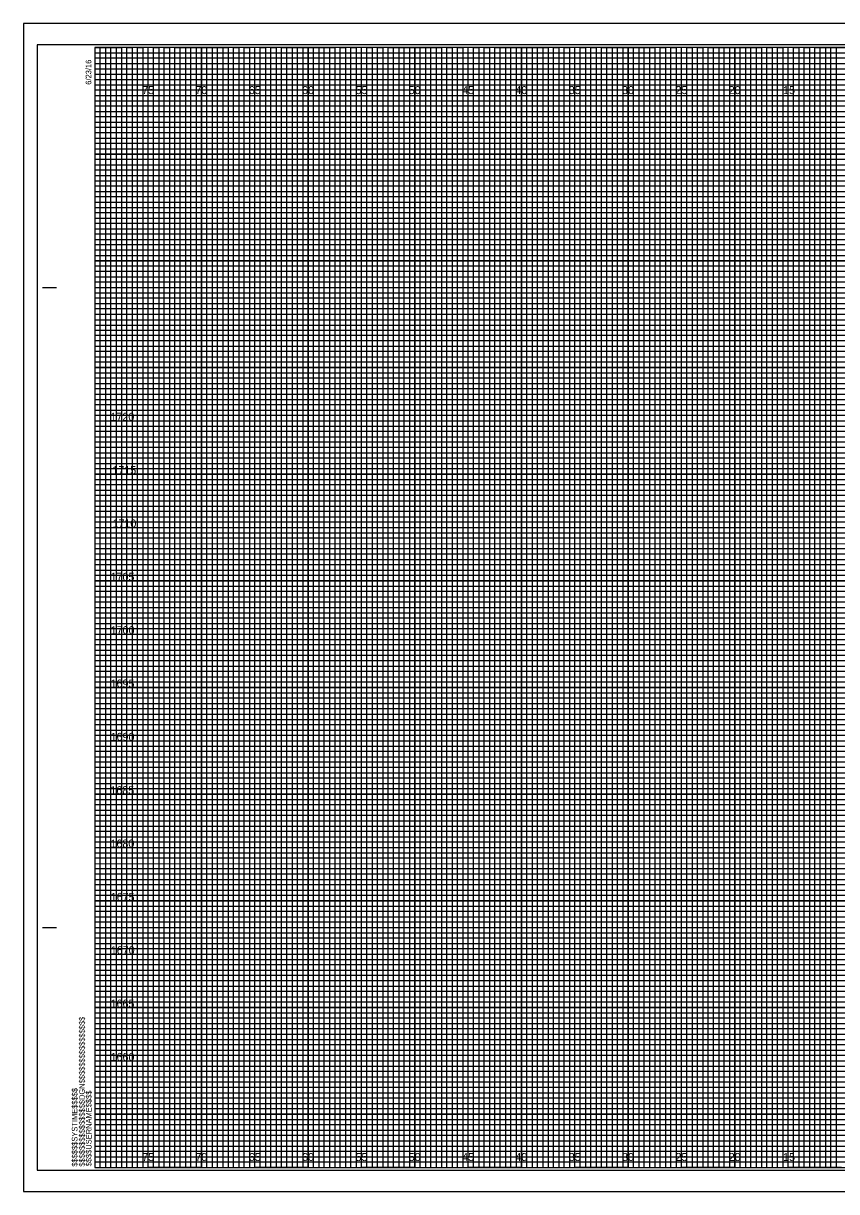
# Model space of a CAD drawing. Extents: x -7 to 162, y -2 to 327.
# Drawn here: x -6.7 to 69.5, y -2.3 to 107.3 of the extents above; entities that cross this region are included whole.
import ezdxf

# ---------------------------------------------------------------- set-up
doc = ezdxf.new("R2010")
doc.units = 0
for name, color, linetype in [('Raster_Level_0', 7, 'Continuous'), ('Scratch_Level_3', 7, 'Continuous'), ('Sheet Cross Section CELL', 7, 'Continuous'), ('Sheet Cross Section Grid Major CELL', 7, 'Continuous'), ('Sheet Cross Section Grid Middle CELL', 7, 'Continuous'), ('Sheet Cross Section Grid Minor 1 CELL', 7, 'Continuous'), ('Sheet Cross Section Grid Minor 2 CELL', 7, 'Continuous'), ('Sheet Cutting Line CELL', 7, 'Continuous'), ('Sheet DOT Grid CELL', 7, 'Continuous'), ('Sheet Plot Border Inside CELL', 7, 'Continuous'), ('Sheet Plot Border Outside CELL', 7, 'Continuous')]:
    doc.layers.add(name, color=color, linetype=linetype)

msp = doc.modelspace()

# ---------------------------------------------------------------- linework, layer by layer
at = {"layer": 'Sheet Cross Section CELL'}
for p, q in [((-4.9, 82.5), (-3.65, 82.5)), ((-4.85, 82.5), (-3.6, 82.5)), ((-4.9, 22.5), (-3.65, 22.5)), ((-4.85, 22.5), (-3.6, 22.5)), ((0, 0), (0, 0)), ((0, 0), (0, 0)), ((0, 0), (0, 0)), ((0, 0), (0, 0)), ((0, 0), (0, 0)), ((0, 0), (0, 0)), ((0, 0), (0, 0))]:
    msp.add_line(p, q, dxfattribs=at)
msp.add_lwpolyline([(160, 105), (0, 105), (0, 0), (160, 0)], close=True, dxfattribs=at)
at = {"layer": 'Sheet Cross Section Grid Major CELL'}
for p, q in [((5, 105), (0, 105)), ((5, 0), (5, 105)), ((15, 105), (10, 105)), ((10, 105), (10, 0)), ((15, 0), (15, 105)), ((25, 105), (20, 105)), ((20, 105), (20, 0)), ((25, 0), (25, 105)), ((35, 105), (30, 105)), ((30, 105), (30, 0)), ((35, 0), (35, 105)), ((45, 105), (40, 105)), ((40, 105), (40, 0)), ((45, 0), (45, 105)), ((55, 105), (50, 105)), ((50, 105), (50, 0)), ((55, 0), (55, 105)), ((65, 105), (60, 105)), ((60, 105), (60, 0)), ((65, 0), (65, 105)), ((10, 0), (5, 0)), ((20, 0), (15, 0)), ((30, 0), (25, 0)), ((40, 0), (35, 0)), ((50, 0), (45, 0)), ((60, 0), (55, 0)), ((70, 0), (65, 0))]:
    msp.add_line(p, q, dxfattribs=at)
for points in [[(0, 100), (160, 100), (160, 95), (0, 95)], [(0, 90), (160, 90), (160, 85), (0, 85)], [(0, 80), (160, 80), (160, 75), (0, 75)], [(0, 70), (160, 70), (160, 65), (0, 65)], [(0, 60), (160, 60), (160, 55), (0, 55)], [(0, 50), (160, 50), (160, 45), (0, 45)], [(0, 40), (160, 40), (160, 35), (0, 35)], [(0, 30), (160, 30), (160, 25), (0, 25)], [(0, 20), (160, 20), (160, 15), (0, 15)], [(0, 10), (160, 10), (160, 5), (0, 5)]]:
    msp.add_lwpolyline(points, dxfattribs=at)
at = {"layer": 'Sheet Cross Section Grid Middle CELL'}
for points in [[(0, 105), (2.5, 105), (2.5, 0), (7.5, 0), (7.5, 105), (12.5, 105), (12.5, 0), (17.5, 0), (17.5, 105), (22.5, 105), (22.5, 0), (27.5, 0), (27.5, 105), (32.5, 105), (32.5, 0), (37.5, 0), (37.5, 105), (42.5, 105), (42.5, 0), (47.5, 0), (47.5, 105), (52.5, 105), (52.5, 0), (57.5, 0), (57.5, 105), (62.5, 105), (62.5, 0), (67.5, 0), (67.5, 105), (72.5, 105)], [(0, 102.5), (137.5, 102.5)], [(0, 92.5), (160, 92.5), (160, 97.5), (0, 97.5)], [(0, 82.5), (160, 82.5), (160, 87.5), (0, 87.5)], [(0, 72.5), (160, 72.5), (160, 77.5), (0, 77.5)], [(0, 62.5), (160, 62.5), (160, 67.5), (0, 67.5)], [(0, 52.5), (160, 52.5), (160, 57.5), (0, 57.5)], [(0, 42.5), (160, 42.5), (160, 47.5), (0, 47.5)], [(0, 32.5), (160, 32.5), (160, 37.5), (0, 37.5)], [(0, 22.5), (160, 22.5), (160, 27.5), (0, 27.5)], [(0, 12.5), (160, 12.5), (160, 17.5), (0, 17.5)], [(0, 2.5), (160, 2.5), (160, 7.5), (0, 7.5)]]:
    msp.add_lwpolyline(points, dxfattribs=at)
at = {"layer": 'Sheet Cross Section Grid Minor 1 CELL'}
for p, q in [((0, 104.5), (130, 104.5)), ((130, 103.99), (0, 103.99)), ((0, 103.99), (0, 103.5)), ((0, 103.5), (130, 103.5)), ((130, 102.95), (0, 102.95)), ((0, 102.95), (0, 102)), ((0, 102), (160, 102))]:
    msp.add_line(p, q, dxfattribs=at)
for points in [[(0, 101.5), (135, 101.5), (160, 101.5), (160, 101), (0, 101)], [(0, 100.5), (160, 100.5), (160, 99.5), (0, 99.5)], [(0, 99), (160, 99), (160, 98.5), (0, 98.49)], [(0, 98), (160, 98), (160, 97), (0, 97)], [(0, 96.5), (160, 96.5), (160, 96), (0, 96)], [(0, 95.5), (160, 95.5), (160, 94.5), (0, 94.5)], [(0, 94), (160, 94), (160, 93.5), (0, 93.5)], [(0, 93), (160, 93), (160, 92), (0, 92)], [(0, 91.5), (160, 91.5), (160, 91), (0, 91)], [(0, 90.5), (160, 90.5), (160, 89.5), (0, 89.5)], [(0, 89), (160, 89), (160, 88.5), (0, 88.5)], [(0, 88), (160, 88), (160, 86.98), (160, 86.5), (160, 86), (0, 86)], [(0, 87), (160, 87), (160, 86.5), (0, 86.5)], [(0, 85.5), (160, 85.5), (160, 84.5), (0, 84.52)], [(0, 84.52), (160, 84.5), (160, 84), (0, 84)], [(0, 83.5), (160, 83.5), (160, 83), (0, 83)], [(0, 82), (160, 82), (160, 81.5), (0, 81.5)], [(0, 81), (160, 81), (160, 80.5), (0, 80.5)], [(-0.04, 79.45), (160, 79.45), (160, 78.94), (-0.04, 78.94)], [(0, 78.5), (160, 78.5), (160, 78), (0, 78)], [(0, 77), (160, 77), (160, 76.5), (0, 76.5)], [(0, 76), (160, 76), (160, 75.5), (0, 75.5)], [(0, 74.5), (160, 74.5), (160, 74), (0, 74)], [(0, 73.5), (160, 73.5), (160, 73), (0, 73)], [(0, 72), (160, 72), (160, 71.5), (0, 71.5)], [(0, 71), (160, 71), (160, 70.5), (0, 70.5)], [(0, 69.5), (160, 69.5), (160, 68.99), (0, 69)], [(0, 68.5), (160, 68.5), (160, 68), (0, 68)], [(0, 67), (160, 67), (160, 66.5), (0, 66.5)], [(0, 66), (160, 66), (160, 65.5), (0, 65.5)], [(0, 64.5), (160, 64.5), (160, 64), (0, 64)], [(0, 63.5), (160, 63.5), (160, 63), (0, 63)], [(0, 62), (160, 62), (160, 61.5), (0, 61.5)], [(0, 61), (160, 61), (160, 60.5), (0, 60.5)], [(0, 59.5), (160, 59.5), (160, 59), (0, 59)], [(0, 58.5), (160.03, 58.45), (160, 58), (0, 58)], [(0, 57), (160, 57), (160, 56.5), (0, 56.5)], [(0, 56), (160, 56), (160, 55.5), (0, 55.5)], [(0, 54.5), (160, 54.5), (160, 54), (0, 54)], [(0, 53.5), (160, 53.5), (160, 53), (0, 53)], [(0, 52), (160, 52), (160, 51.5), (0, 51.5)], [(0, 51), (160, 51), (160, 50.5), (0, 50.5)], [(0, 49.5), (160, 49.5), (160, 49), (0, 49)], [(0, 48.5), (160, 48.5), (160, 48), (0, 48)], [(0, 47), (160, 47), (160, 46.5), (0, 46.5)], [(0, 46), (160, 46), (160, 45.5), (0, 45.5)], [(0, 44.5), (160, 44.5), (160, 44), (0, 44)], [(0, 43.5), (160, 43.5), (160, 43), (0, 43)], [(0, 42), (160, 42), (160, 41.5), (0, 41.5)], [(0, 41), (160, 41), (160, 40.5), (0, 40.5)], [(0, 39.5), (160, 39.5), (160, 38.99), (0, 39)], [(0, 38.5), (160, 38.5), (160, 38), (0, 38)], [(0, 37), (160, 37), (160, 36.5), (0, 36.5)], [(0, 36), (160, 36), (160, 35.5), (0, 35.5)], [(0, 34.5), (160, 34.5), (160, 34), (0, 34)], [(0, 33.5), (160, 33.5), (160, 33), (0, 33)], [(0, 32), (160, 32), (160, 31.5), (0, 31.5)], [(0, 31), (160, 31), (160, 30.5), (0, 30.5)], [(0, 29.5), (160, 29.5), (160, 29), (0, 29)], [(0, 28.5), (160.03, 28.46), (160, 28), (0, 28)], [(0, 27), (160, 27), (160, 26.5), (0, 26.5)], [(0, 26), (160, 26), (160, 25.5), (0, 25.5)], [(0, 24.5), (160, 24.5), (160, 24), (0, 24)], [(0, 23.5), (160, 23.5), (160, 23), (0, 23)], [(0, 22), (160, 22), (160, 21.5), (0, 21.5)], [(0, 21), (160, 21), (160, 20.5), (0, 20.5)], [(0, 19.5), (160, 19.5), (160, 19), (0, 19)], [(0, 18.5), (160, 18.5), (160, 18), (0, 18)], [(0, 17), (160, 17), (160, 16.5), (0, 16.5)], [(0, 16), (160, 16), (160, 15.5), (0, 15.5)], [(0, 14.5), (160, 14.5), (160, 14), (0, 14)], [(0, 13.5), (160, 13.5), (160, 13), (0, 13)], [(0, 12), (160, 12), (160, 11.5), (0, 11.5)], [(0, 11), (160, 11), (160, 10.5), (0, 10.5)], [(0, 9.5), (160, 9.5), (160, 9), (0, 9)], [(0, 8.5), (160, 8.5), (160, 8), (0, 8)], [(0, 7), (160, 7), (160, 6.5), (0, 6.5)], [(0, 6), (160, 6), (160, 5.5), (0, 5.5)], [(0, 4.5), (160, 4.5), (160, 4), (0, 4)], [(0, 3.5), (160, 3.5), (160, 3), (0, 3)], [(0, 2), (160, 2), (160, 1.5), (0, 1.5)], [(0, 1), (160, 1), (160, 0.5), (0, 0.5)]]:
    msp.add_lwpolyline(points, dxfattribs=at)
at = {"layer": 'Sheet Cross Section Grid Minor 2 CELL'}
for points in [[(0, 0), (0.5, 0), (0.5, 105), (1, 105), (1, 0)], [(1, 0), (1.5, 0), (1.5, 105), (2, 105), (2, 0)], [(2.5, 0), (3, 0), (3, 105), (3.5, 105), (3.5, 0)], [(3.5, 0), (4, 0), (4, 105), (4.5, 105), (4.5, 0)], [(5, 0), (5.5, 0), (5.5, 105), (6, 105), (6, 0)], [(6, 0), (6.5, 0), (6.5, 105), (7, 105), (7, 0)], [(7.5, 0), (8, 0), (8, 105), (8.5, 105), (8.5, 0)], [(8.5, 0), (9, 0), (9, 105), (9.5, 105), (9.5, 0)], [(10, 0), (10.5, 0), (10.5, 105), (11, 105), (11, 0)], [(11, 0), (11.5, 0), (11.5, 105), (12, 105), (12, 0)], [(12.5, 0), (13, 0), (13, 105), (13.5, 105), (13.5, 0)], [(13.5, 0), (14, 0), (14, 105), (14.5, 105), (14.5, 0)], [(15, 0), (15.5, 0), (15.5, 105), (16, 105), (16, 0)], [(16, 0), (16.5, 0), (16.5, 105), (17, 105), (17, 0)], [(17.5, 0), (18, 0), (18, 105), (18.5, 105), (18.5, 0)], [(18.5, 0), (19, 0), (19, 105), (19.5, 105), (19.5, 0)], [(20, 0), (20.5, 0), (20.5, 105), (21, 105), (21, 0)], [(21, 0), (21.5, 0), (21.5, 105), (22, 105), (22, 0)], [(22.5, 0), (23, 0), (23, 105), (23.5, 105), (23.5, 0)], [(23.5, 0), (24, 0), (24, 105), (24.5, 105), (24.5, 0)], [(25, 0), (25.5, 0), (25.5, 105), (26, 105), (26, 0)], [(26, 0), (26.5, 0), (26.5, 105), (27, 105), (27, 0)], [(27.5, 0), (28, 0), (28, 105), (28.5, 105), (28.5, 0)], [(28.5, 0), (29, 0), (29, 105), (29.5, 105), (29.5, 0)], [(30, 0), (30.5, 0), (30.5, 105), (31, 105), (31, 0)], [(31, 0), (31.5, 0), (31.5, 105), (32, 105), (32, 0)], [(32.5, 0), (33, 0), (33, 105), (33.5, 105), (33.5, 0)], [(33.5, 0), (34, 0), (34, 105), (34.5, 105), (34.5, 0)], [(35, 0), (35.5, 0), (35.5, 105), (36, 105), (36, 0)], [(36, 0), (36.5, 0), (36.5, 105), (37, 105), (37, 0)], [(37.5, 0), (38, 0), (38, 105), (38.5, 105), (38.5, 0)], [(38.5, 0), (39, 0), (39, 105), (39.5, 105), (39.5, 0)], [(40, 0), (40.5, 0), (40.5, 105), (41, 105), (41, 0)], [(41, 0), (41.5, 0), (41.5, 105), (42, 105), (42, 0)], [(42.5, 0), (43, 0), (43, 105), (43.5, 105), (43.5, 0)], [(43.5, 0), (44, 0), (44, 105), (44.5, 105), (44.5, 0)], [(45, 0), (45.5, 0), (45.5, 105), (46, 105), (46, 0)], [(46, 0), (46.5, 0), (46.5, 105), (47, 105), (47, 0)], [(47.5, 0), (48, 0), (48, 105), (48.5, 105), (48.5, 0)], [(48.5, 0), (49, 0), (49, 105), (49.5, 105), (49.5, 0)], [(50, 0), (50.5, 0), (50.5, 105), (51, 105), (51, 0)], [(51, 0), (51.5, 0), (51.5, 105), (52, 105), (52, 0)], [(52.5, 0), (53, 0), (53, 105), (53.5, 105), (53.5, 0)], [(53.5, 0), (54, 0), (54, 105), (54.5, 105), (54.5, 0)], [(55, 0), (55.5, 0), (55.5, 105), (56, 105), (56, 0)], [(56, 0), (56.5, 0), (56.5, 105), (57, 105), (57, 0)], [(57.5, 0), (58, 0), (58, 105), (58.5, 105), (58.5, 0)], [(58.5, 0), (59, 0), (59, 105), (59.5, 105), (59.5, 0)], [(60, 0), (60.5, 0), (60.5, 105), (61, 105), (61, 0)], [(61, 0), (61.5, 0), (61.5, 105), (62, 105), (62, 0)], [(62.5, 0), (63, 0), (63, 105), (63.5, 105), (63.5, 0)], [(63.5, 0), (64, 0), (64, 105), (64.5, 105), (64.5, 0)], [(65, 0), (65.5, 0), (65.5, 105), (66, 105), (66, 0)], [(66, 0), (66.5, 0), (66.5, 105), (67, 105), (67, 0)], [(67.5, 0), (68, 0), (68, 105), (68.5, 105), (68.5, 0)], [(68.5, 0), (69, 0), (69, 105), (69.5, 105), (69.5, 0)]]:
    msp.add_lwpolyline(points, dxfattribs=at)
at = {"layer": 'Sheet Cutting Line CELL'}
for p, q in [((161.65, 107.25), (-6.7, 107.25)), ((-6.7, 107.25), (-6.7, -2.25)), ((-6.7, -2.25), (161.65, -2.25))]:
    msp.add_line(p, q, dxfattribs=at)
at = {"layer": 'Sheet DOT Grid CELL'}
for p, q in [((5, 0), (5, 105)), ((10, 0), (10, 105)), ((15, 0), (15, 105)), ((20, 0), (20, 105)), ((25, 0), (25, 105)), ((30, 0), (30, 105)), ((35, 0), (35, 105)), ((40, 0), (40, 105)), ((45, 0), (45, 105)), ((50, 0), (50, 105)), ((55, 0), (55, 105)), ((60, 0), (60, 105)), ((65, 0), (65, 105)), ((0, 100), (160, 100)), ((0, 95), (160, 95)), ((0, 90), (160, 90)), ((0, 85), (160, 85)), ((0, 80), (160, 80)), ((0, 75), (160, 75)), ((0, 70), (160, 70)), ((0, 65), (160, 65)), ((0, 60), (160, 60)), ((0, 55), (160, 55)), ((0, 50), (160, 50)), ((0, 45), (160, 45)), ((0, 40), (160, 40)), ((0, 35), (160, 35)), ((0, 30), (160, 30)), ((0, 25), (160, 25)), ((0, 20), (160, 20)), ((0, 15), (160, 15)), ((0, 10), (160, 10)), ((0, 5), (160, 5))]:
    msp.add_line(p, q, dxfattribs=at)
at = {"layer": 'Sheet Plot Border Inside CELL'}
msp.add_lwpolyline([(-5.4, -0.25), (161.2, -0.25), (161.2, 105.25), (-5.4, 105.25)], close=True, dxfattribs=at)
at = {"layer": 'Sheet Plot Border Outside CELL'}
msp.add_lwpolyline([(-6.7, -2.25), (161.65, -2.25), (161.65, 107.25), (-6.7, 107.25)], close=True, dxfattribs=at)

# ---------------------------------------------------------------- texts
at = {"layer": 'Raster_Level_0'}
for s, p in [('75', (4.44, 100.62)), ('70', (9.43, 100.62)), ('65', (14.44, 100.62)), ('60', (19.43, 100.62)), ('55', (24.44, 100.62)), ('50', (29.43, 100.62)), ('45', (34.44, 100.62)), ('40', (39.43, 100.62)), ('35', (44.44, 100.62)), ('30', (49.43, 100.62)), ('25', (54.44, 100.62)), ('20', (59.43, 100.62)), ('15', (64.53, 100.62)), ('75', (4.44, 0.62)), ('70', (9.43, 0.62)), ('65', (14.44, 0.62)), ('60', (19.43, 0.62)), ('55', (24.44, 0.62)), ('50', (29.43, 0.62)), ('45', (34.44, 0.62)), ('40', (39.43, 0.62)), ('35', (44.44, 0.62)), ('30', (49.43, 0.62)), ('25', (54.44, 0.62)), ('20', (59.43, 0.62)), ('15', (64.53, 0.62))]:
    msp.add_text(s, height=0.75, dxfattribs=at).set_placement(p)
at = {"layer": 'Scratch_Level_3'}
for s, p in [('1720', (1.47, 70)), ('1715', (1.65, 65)), ('1710', (1.66, 60)), ('1705', (1.48, 55)), ('1700', (1.49, 50)), ('1695', (1.48, 45)), ('1690', (1.48, 40)), ('1685', (1.46, 35)), ('1680', (1.47, 30)), ('1675', (1.49, 25)), ('1670', (1.5, 20)), ('1665', (1.48, 15)), ('1660', (1.48, 10))]:
    msp.add_text(s, height=0.75, dxfattribs=at).set_placement(p)
at = {"layer": 'Sheet Cross Section CELL'}
for s, p in [('6/23/16', (-0.33, 101.5)), ('$$$$$$$$$$$$$$$$DGN$$$$$$$$$$$$$$$$', (-0.94, 0.09)), ('$$$$$$SYSTIME$$$$$', (-1.63, 0.09)), ('$$$$USERNAME$$$$', (-0.31, 0.12))]:
    msp.add_text(s, height=0.525, rotation=90, dxfattribs=at).set_placement(p)

doc.saveas('drawing.dxf')
